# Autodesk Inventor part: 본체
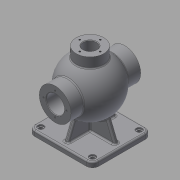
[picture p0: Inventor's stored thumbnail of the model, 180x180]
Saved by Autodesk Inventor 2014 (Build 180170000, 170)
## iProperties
Created: 2015-10
Part Number: 본체
Material: Generic
Document SubType Name: Modeling
Designer: youjin18
Density: 1 g/cm^3
Appearance: Default
Author: youjin18
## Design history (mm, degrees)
sketch "스케치1"
  geometry: L1 (62.5, 57.5)-(-62.5, 57.5); L2 (-62.5, 57.5)-(-62.5, -57.5); L3 (-62.5, -57.5)-(62.5, -57.5); L4 (62.5, -57.5)-(62.5, 57.5); L5 (62.5, 57.5)-(-62.5, -57.5); L6 (-62.5, 57.5)-(62.5, -57.5); 1 further point
  constraints: 12 end point, 2 midpoint, 2 parallel, 1 horizontal, 1 perpendicular
  dimensions: "d0" = 125 distance of L3.end L2.end; "d1" = 115 distance of L2.end L1.end
extrude "돌출1" new body sketch "스케치1" distance "d2" = 10; taper "d3" = 0 deg
fillet "모깎기1" dims "d4" = 12
sketch "스케치2"
  geometry: A1 r 12 centre (50.5, -45.5) between (50.5, -57.5) and (62.5, -45.5) reference; A2 r 12 centre (50.5, 45.5) between (62.5, 45.5) and (50.5, 57.5) reference; A3 r 12 centre (-50.5, 45.5) between (-50.5, 57.5) and (-62.5, 45.5) reference; A4 r 12 centre (-50.5, -45.5) between (-62.5, -45.5) and (-50.5, -57.5) reference; 5 further points
  constraints: 4 coincident
hole "구멍1" sketch "스케치2" at (-50.5, 45.5), (50.5, 45.5), (50.5, -45.5), (-50.5, -45.5) diameter "d5" = 8; stored, may be unused: countersink angle "d9" = 90 deg, drill point angle "d11" = 118 deg; dims "d6" = 6, "d7" = 12, "d8" = 3, "d10" = 8
sketch "스케치3"
  geometry: L1 (-16.741, 34.713)-(16.741, 135.287); C1 r 53 at (0, 85); A1 r 53 centre (0, 85) between (-16.741, 34.713) and (16.741, 135.287); 1 further point
  constraints: 2 centre point, 2 end point, 2 point on circle, 1 coincident, 1 midpoint, 1 vertical alignment
  dimensions: "d12" = 106 diameter of C1; "d13" = 85 distance of point (0, 0) C1.centre; "d14" = 106 diameter of A1
revolve "회전1" sketch "스케치3" stored, may be unused: angle "d15" = 90 deg
sketch "스케치4"
  geometry: C1 r 31 at (0, 85); 1 further point
  constraints: 1 centre point, 1 vertical alignment
  dimensions: "d16" = 62 diameter of C1; "d17" = 85 distance of point (0, 0) C1.centre
extrude "돌출2" join sketch "스케치4" stored distance "d18" = 136; taper "d19" = 0 deg
node "작업 평면1"
sketch "스케치5"
  geometry: C1 r 27 at (0, 0); 1 further point
  constraints: 1 centre point, 1 coincident
  dimensions: "d21" = 54 diameter of C1
extrude "돌출3" join sketch "스케치5" stored distance "d22" = 136; taper "d23" = 0 deg
sketch "스케치7"
  geometry: L1 (45.5, 10)-(-45.5, 10) reference; L2 (-33.719, 44.109)-(-47.5, 10); L3 (33.719, 44.109)-(47.5, 10); L4 (57.5, 10)-(57.5, 0) reference; L5 (-57.5, 0)-(-57.5, 10) reference; A1 r 53 centre (0, 85) between (42.988, 116) and (42.988, 54) reference; 1 further point
  constraints: 4 end point, 2 point on circle, 2 point on line
  dimensions: "d30" = 22 deg angle of L4 L3; "d31" = 22 deg angle of L5 L2; "d32" = 10 distance from line of L5 L2.end; "d33" = 10 horizontal distance of L4.end L3.end
sketch "스케치8"
  geometry: L1 (32.24, 56.547)-(-32.24, 113.453); A1 r 53 centre (0, 85) between (-27, 130.607) and (27, 130.607) reference; A2 r 43 centre (0, 85) between (32.24, 56.547) and (-32.24, 113.453); 1 further point
  constraints: 2 end point, 2 point on circle, 1 centre point, 1 coincident, 1 midpoint
  dimensions: "d46" = 86 diameter of A2
revolve "회전2" sketch "스케치8" stored, may be unused: angle "d47" = 90 deg
sketch "스케치9"
  geometry: C1 r 31 at (0, 0) reference; C2 r 17.5 at (0, 0); 1 further point
  constraints: 1 centre point, 1 coincident
  dimensions: "d48" = 35 diameter of C2
extrude "돌출5" cut sketch "스케치9" stored distance "d49" = 8; taper "d50" = 0 deg
chamfer "모따기1" distance "d51" = 1; stored, may be unused: second distance "d52" = 2, angle "d53" = 45 deg
sketch "스케치10"
  geometry: C1 r 31 at (0, 0) reference; C2 r 18.5 at (0, 0) reference; A1 r 22.5 centre (0, 0) between (0, 22.5) and (-22.5, 0); 3 further points
  constraints: 4 point on circle, 2 horizontal alignment, 2 vertical alignment, 1 centre point, 1 coincident
  dimensions: "d54" = 45 diameter of A1
hole "구멍2" sketch "스케치10" at (0, -22.5), (-22.5, 0), (0, 22.5), (22.5, 0) diameter "d55" = 3.242; stored, may be unused: countersink angle "d59" = 90 deg, drill point angle "d61" = 118 deg; dims "d56" = 12, "d57" = 12, "d58" = 3, "d60" = 15
sketch "스케치11"
  geometry: C1 r 31 at (0, 0) reference; C2 r 18.5 at (0, 0) reference; A1 r 24 centre (0, 0) between (0, 24) and (-24, 0); 3 further points
  constraints: 4 point on circle, 2 vertical alignment, 1 centre point, 1 coincident, 1 horizontal alignment
  dimensions: "d62" = 48 diameter of A1
hole "구멍3" sketch "스케치11" at (0, 24), (-24, 0), (0, -24), (23.561, -4.571) diameter "d63" = 3.242; stored, may be unused: countersink angle "d67" = 90 deg, drill point angle "d69" = 118 deg; dims "d64" = 16, "d65" = 12, "d66" = 3, "d68" = 19
node "작업 평면2"
sketch "스케치12"
  geometry: C1 r 31 at (0, 85) reference; C2 r 18.5 at (0, 85); C3 r 17.5 at (0, 85) reference; 1 further point
  constraints: 1 centre point, 1 coincident
  dimensions: "d71" = 37 diameter of C2
extrude "돌출6" cut sketch "스케치12" distance "d72" = 1.75; taper "d73" = 0 deg
sketch "스케치13"
  geometry: C1 r 27 at (0, 0) reference; C2 r 13 at (0, 0)
  constraints: 1 centre point, 1 coincident
  dimensions: "d74" = 26 diameter of C2
extrude "돌출7" cut sketch "스케치13" stored distance "d75" = 1.75; taper "d76" = 0 deg
chamfer "모따기2" distance "d77" = 1; stored, may be unused: second distance "d78" = 2, angle "d79" = 45 deg
sketch "스케치14"
  geometry: C1 r 27 at (0, 0) reference; C2 r 14 at (0, 0) reference; A1 r 20 centre (0, 0) between (0, 20) and (-20, 0); 2 further points
  constraints: 4 point on circle, 2 horizontal alignment, 2 vertical alignment, 1 centre point, 1 coincident
  dimensions: "d80" = 40 diameter of A1
hole "구멍4" sketch "스케치14" at (0, 20), (-20, 0), (0, -20), (20, 0) diameter "d81" = 3.242; stored, may be unused: countersink angle "d85" = 90 deg, drill point angle "d87" = 118 deg; dims "d82" = 9, "d83" = 12, "d84" = 3, "d86" = 11
fillet "모깎기2" dims "d88" = 3
sketch "스케치16"
  geometry: L1 (4, 4)-(-4, 4); L2 (-4, 4)-(-4, -4); L3 (-4, -4)-(4, -4); L4 (4, -4)-(4, 4); L5 (4, 4)-(-4, -4); L6 (-4, 4)-(4, -4); 1 further point
  constraints: 12 end point, 2 midpoint, 2 parallel, 1 horizontal, 1 perpendicular
  dimensions: "d94" = 8 distance of L3.end L2.end; "d95" = 8 distance of L2.end L1.end
extrude "돌출9" join sketch "스케치16" stored distance "d96" = 1.75; taper "d97" = 0 deg
feature "리브3" dims "d98" = 1, "d99" = 8, "d100" = 0, "d101" = 0, "d102" = 1, "d103" = 1
feature "리브4" dims "d104" = 1, "d105" = 8, "d106" = 0, "d107" = 0, "d108" = 1, "d109" = 1
sketch "스케치17"
  geometry: L1 (50.5, 10)-(-50.5, 10) reference; L2 (-37.379, 47.426)-(-52.5, 10); L3 (37.379, 47.426)-(52.5, 10); L4 (62.5, 10)-(62.5, 0) reference; L5 (-62.5, 0)-(-62.5, 10) reference; A1 r 53 centre (0, 85) between (-28.393, 129.753) and (28.393, 129.753) reference; 1 further point
  constraints: 4 end point, 2 point on circle, 2 point on line
  dimensions: "d110" = 22 deg angle of L4 L3; "d111" = 22 deg angle of L5 L2; "d112" = 10 distance from line of L5 L2.end; "d113" = 10 distance from line of L4 L3.end
feature "리브5" dims "d114" = 1, "d115" = 8, "d116" = 0, "d117" = 0, "d118" = 1, "d119" = 1
feature "리브6" dims "d120" = 1, "d121" = 8, "d122" = 0, "d123" = 0, "d124" = 1, "d125" = 1
fillet "모깎기4" dims "d126" = 3
fillet "모깎기5" dims "d127" = 3
node "작업 평면3"
sketch "스케치18"
  geometry: L1 (-27, 0)-(-27, -17.714) reference; L2 (-27, 0)-(27, 0) reference; 2 further points
  constraints: 1 vertical alignment, 1 other
  dimensions: "d128" = 27 distance from line of point (0, -10) L1 (derived); "d129" = 10 distance from line of L2 point (0, -10)
feature "엠보싱1" sketch "스케치18" dims "d0" = 125, "d1" = 115, "d130" = 0.5, "d131" = 0
node "솔리드1"
other parameters: "d70" = 52
